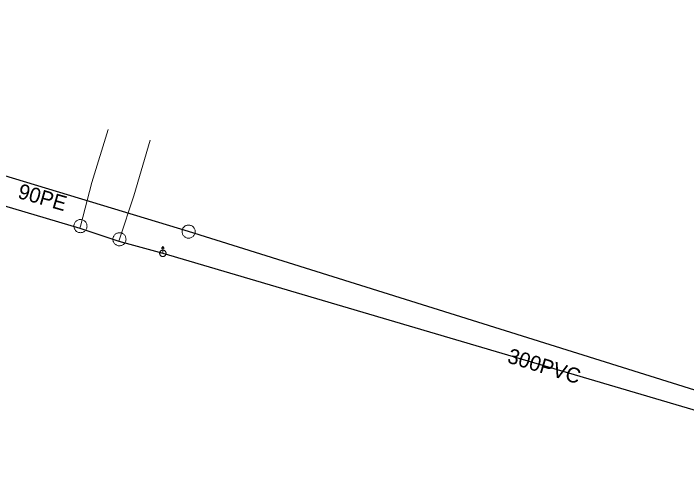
# Model space of a CAD drawing. Extents: x -741806 to -738704, y -1059275 to -1055387.
# Drawn here: x -740379 to -740334.15, y -1057289.5 to -1057258.67 of the extents above; entities that cross this region are included whole.
import ezdxf

# ---------------------------------------------------------------- set-up
doc = ezdxf.new("R2010")
doc.units = 0
doc.header["$LTSCALE"] = 0.4
for name, color, linetype, lineweight in [('2', 7, 'Continuous', 25), ('21', 7, 'Continuous', 13), ('3', 7, 'Continuous', 13), ('36', 7, 'Continuous', 13), ('51', 7, 'Continuous', 13), ('52', 7, 'Continuous', 25)]:
    doc.layers.add(name, color=color, linetype=linetype, lineweight=lineweight)
doc.layers.add('5', color=7, linetype='Continuous')
doc.layers.add('53', color=7, linetype='Continuous')

msp = doc.modelspace()

# ---------------------------------------------------------------- linework, layer by layer
at = {"layer": '2'}
msp.add_lwpolyline([(-740318.07, -1057288.6), (-740320.633, -1057287.799), (-740367.329, -1057273.19), (-740415.289, -1057258.669)], dxfattribs=at)
at = {"layer": '21'}
for points in [[(-740374.585, -1057272.968), (-740374.537, -1057272.825), (-740373.772, -1057269.915), (-740372.682, -1057266.392)], [(-740371.978, -1057273.828), (-740371.938, -1057273.7), (-740370.978, -1057270.808), (-740369.881, -1057267.097)]]:
    msp.add_lwpolyline(points, dxfattribs=at)
at = {"layer": '3'}
msp.add_lwpolyline([(-740366.891, -1057273.19), (-740366.894, -1057273.145), (-740366.901, -1057273.1), (-740366.913, -1057273.055), (-740366.929, -1057273.013), (-740366.95, -1057272.972), (-740366.975, -1057272.933), (-740367.004, -1057272.898), (-740367.036, -1057272.865), (-740367.072, -1057272.837), (-740367.11, -1057272.812), (-740367.151, -1057272.791), (-740367.194, -1057272.774), (-740367.238, -1057272.763), (-740367.283, -1057272.755), (-740367.329, -1057272.753), (-740367.375, -1057272.755), (-740367.42, -1057272.763), (-740367.464, -1057272.774), (-740367.507, -1057272.791), (-740367.548, -1057272.812), (-740367.586, -1057272.837), (-740367.621, -1057272.865), (-740367.654, -1057272.898), (-740367.683, -1057272.933), (-740367.708, -1057272.972), (-740367.728, -1057273.013), (-740367.745, -1057273.055), (-740367.757, -1057273.1), (-740367.764, -1057273.145), (-740367.766, -1057273.191), (-740367.764, -1057273.236), (-740367.757, -1057273.281), (-740367.745, -1057273.326), (-740367.728, -1057273.369), (-740367.708, -1057273.409), (-740367.683, -1057273.448), (-740367.654, -1057273.483), (-740367.621, -1057273.516), (-740367.586, -1057273.544), (-740367.548, -1057273.569), (-740367.507, -1057273.59), (-740367.464, -1057273.607), (-740367.42, -1057273.619), (-740367.375, -1057273.626), (-740367.329, -1057273.628), (-740367.283, -1057273.626), (-740367.238, -1057273.619), (-740367.194, -1057273.607), (-740367.151, -1057273.59), (-740367.11, -1057273.569), (-740367.072, -1057273.544), (-740367.036, -1057273.516), (-740367.004, -1057273.483), (-740366.975, -1057273.448), (-740366.95, -1057273.409), (-740366.929, -1057273.368), (-740366.913, -1057273.326), (-740366.901, -1057273.281), (-740366.894, -1057273.236), (-740366.891, -1057273.191)], dxfattribs=at)
at = {"layer": '36'}
msp.add_line((-740369.045, -1057274.188), (-740368.948, -1057274.32), dxfattribs=at)
msp.add_lwpolyline([(-740368.833, -1057274.636), (-740368.833, -1057274.613), (-740368.836, -1057274.592), (-740368.842, -1057274.57), (-740368.85, -1057274.549), (-740368.86, -1057274.529), (-740368.872, -1057274.511), (-740368.886, -1057274.493), (-740368.902, -1057274.477), (-740368.92, -1057274.463), (-740368.938, -1057274.451), (-740368.958, -1057274.441), (-740368.979, -1057274.433), (-740369, -1057274.427), (-740369.022, -1057274.424), (-740369.045, -1057274.423), (-740369.067, -1057274.424), (-740369.089, -1057274.427), (-740369.111, -1057274.433), (-740369.131, -1057274.441), (-740369.151, -1057274.451), (-740369.17, -1057274.463), (-740369.187, -1057274.477), (-740369.203, -1057274.493), (-740369.217, -1057274.511), (-740369.229, -1057274.529), (-740369.239, -1057274.549), (-740369.247, -1057274.57), (-740369.253, -1057274.592), (-740369.257, -1057274.613), (-740369.259, -1057274.636), (-740369.258, -1057274.658), (-740369.254, -1057274.68), (-740369.248, -1057274.702), (-740369.24, -1057274.722), (-740369.23, -1057274.742), (-740369.218, -1057274.761), (-740369.204, -1057274.778), (-740369.188, -1057274.794), (-740369.171, -1057274.808), (-740369.152, -1057274.82), (-740369.132, -1057274.83), (-740369.112, -1057274.838), (-740369.09, -1057274.844), (-740369.068, -1057274.848), (-740369.046, -1057274.849), (-740369.023, -1057274.848), (-740369.001, -1057274.844), (-740368.98, -1057274.838), (-740368.959, -1057274.83), (-740368.939, -1057274.82), (-740368.921, -1057274.808), (-740368.903, -1057274.794), (-740368.887, -1057274.778), (-740368.873, -1057274.761), (-740368.861, -1057274.742), (-740368.851, -1057274.722), (-740368.843, -1057274.702), (-740368.837, -1057274.68), (-740368.834, -1057274.658)], close=True, dxfattribs=at)
msp.add_lwpolyline([(-740369.046, -1057274.636), (-740369.045, -1057274.188), (-740369.142, -1057274.32)], dxfattribs=at)
at = {"layer": '51'}
for points in [[(-740374.396, -1057272.411), (-740374.439, -1057272.398), (-740374.484, -1057272.39), (-740374.531, -1057272.387), (-740374.576, -1057272.389), (-740374.621, -1057272.396), (-740374.666, -1057272.407), (-740374.709, -1057272.423), (-740374.75, -1057272.443), (-740374.788, -1057272.468), (-740374.824, -1057272.496), (-740374.857, -1057272.528), (-740374.887, -1057272.564), (-740374.912, -1057272.601), (-740374.933, -1057272.642), (-740374.95, -1057272.685), (-740374.963, -1057272.729), (-740374.971, -1057272.774), (-740374.973, -1057272.819), (-740374.971, -1057272.866), (-740374.964, -1057272.911), (-740374.953, -1057272.955), (-740374.938, -1057272.998), (-740374.917, -1057273.039), (-740374.893, -1057273.078), (-740374.864, -1057273.114), (-740374.832, -1057273.147), (-740374.797, -1057273.176), (-740374.758, -1057273.201), (-740374.718, -1057273.222), (-740374.675, -1057273.24), (-740374.632, -1057273.251), (-740374.587, -1057273.259), (-740374.54, -1057273.262), (-740374.495, -1057273.261), (-740374.45, -1057273.254), (-740374.405, -1057273.243), (-740374.363, -1057273.226), (-740374.321, -1057273.207), (-740374.283, -1057273.181), (-740374.247, -1057273.153), (-740374.214, -1057273.121), (-740374.184, -1057273.086), (-740374.16, -1057273.048), (-740374.138, -1057273.008), (-740374.121, -1057272.965), (-740374.108, -1057272.921), (-740374.101, -1057272.876), (-740374.098, -1057272.83), (-740374.1, -1057272.784), (-740374.107, -1057272.739), (-740374.118, -1057272.695), (-740374.133, -1057272.651), (-740374.154, -1057272.611), (-740374.178, -1057272.572), (-740374.207, -1057272.536), (-740374.239, -1057272.503), (-740374.274, -1057272.474), (-740374.313, -1057272.448), (-740374.353, -1057272.427), (-740374.395, -1057272.411)], [(-740371.808, -1057273.282), (-740371.851, -1057273.271), (-740371.896, -1057273.264), (-740371.943, -1057273.262), (-740371.988, -1057273.265), (-740372.033, -1057273.273), (-740372.078, -1057273.285), (-740372.12, -1057273.303), (-740372.161, -1057273.324), (-740372.198, -1057273.35), (-740372.233, -1057273.379), (-740372.265, -1057273.411), (-740372.294, -1057273.447), (-740372.319, -1057273.486), (-740372.339, -1057273.527), (-740372.354, -1057273.57), (-740372.366, -1057273.615), (-740372.373, -1057273.66), (-740372.374, -1057273.705), (-740372.371, -1057273.751), (-740372.363, -1057273.797), (-740372.35, -1057273.841), (-740372.334, -1057273.883), (-740372.312, -1057273.924), (-740372.287, -1057273.962), (-740372.257, -1057273.997), (-740372.225, -1057274.029), (-740372.189, -1057274.057), (-740372.15, -1057274.082), (-740372.109, -1057274.102), (-740372.066, -1057274.118), (-740372.022, -1057274.129), (-740371.977, -1057274.135), (-740371.93, -1057274.137), (-740371.885, -1057274.134), (-740371.84, -1057274.127), (-740371.795, -1057274.114), (-740371.753, -1057274.097), (-740371.712, -1057274.076), (-740371.675, -1057274.05), (-740371.64, -1057274.021), (-740371.608, -1057273.988), (-740371.579, -1057273.952), (-740371.555, -1057273.913), (-740371.534, -1057273.873), (-740371.519, -1057273.829), (-740371.507, -1057273.785), (-740371.501, -1057273.739), (-740371.499, -1057273.694), (-740371.502, -1057273.648), (-740371.51, -1057273.603), (-740371.523, -1057273.559), (-740371.539, -1057273.516), (-740371.561, -1057273.476), (-740371.586, -1057273.438), (-740371.616, -1057273.403), (-740371.649, -1057273.37), (-740371.684, -1057273.343), (-740371.723, -1057273.318), (-740371.764, -1057273.298), (-740371.807, -1057273.283)]]:
    msp.add_lwpolyline(points, dxfattribs=at)
at = {"layer": '52'}
msp.add_lwpolyline([(-740407.857, -1057263.098), (-740407.578, -1057263.179), (-740374.585, -1057272.968), (-740371.978, -1057273.828), (-740369.046, -1057274.632), (-740326.969, -1057287.04), (-740319.489, -1057289.497)], dxfattribs=at)

# ---------------------------------------------------------------- texts
at = {"layer": '5'}
msp.add_text('300PVC', height=1, rotation=343, dxfattribs=at).set_placement((-740346.155, -1057281.894))
at = {"layer": '53'}
msp.add_text('90PE', height=1, rotation=344, dxfattribs=at).set_placement((-740378.773, -1057270.938))

doc.saveas('drawing.dxf')
